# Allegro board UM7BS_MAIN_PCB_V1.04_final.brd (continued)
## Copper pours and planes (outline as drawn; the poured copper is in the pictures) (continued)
VDD33 on BOTTOM (solid shape): 119.28,35.94 119.28,35.89 119.27,35.87 119.23,35.79 119.22,35.7 119.22,35.42 119.11,35.31 118.71,35.31 117.8,34.4 117.8,31.57 117.06,30.83 117.06,29.96 116.76,29.67 114.69,29.67 114.62,29.73 113.35,29.73 113.23,29.86 113.23,31.76 113.3,31.84 114.53,31.84 114.71,32.02 115.93,32.02 116.27,32.36 116.27,33.58 115.98,33.88 115.98,35.21 116.05,35.28 117.02,35.28 117.8,36.06 117.8,36.06 119.15,36.06
VDD33 on LAY4 (solid shape): outline of 746 points within 116.62,31.79 130.86,41.4
VDDIO_8625 on TOP (solid shape): outline of 346 points within 147.79,89.33 153.59,100.76
VDDQ_LX on TOP (solid shape): 199.99,26.54 199.99,22.3 199.68,22 198.69,22 198.69,22 198.22,22 198.05,21.82 198.05,20.95 197.56,20.47 194.71,20.47 194.41,20.77 194.41,26.38 194.83,26.8 199.72,26.8
VIN_LCD on TOP (solid shape): 135.47,94.88 135.55,94.84 135.57,94.76 135.91,94.34 136.26,94.76 136.28,94.84 136.36,94.88 139.01,94.88 139.17,94.72 139.17,93.89 139.65,93.41 139.65,85.62 139.45,85.42 137.2,85.42 136.7,85.92 136.7,89.22 136.13,89.79 135.02,89.79 134.5,90.32 134.5,94.49 134.88,94.88
+V_ADP_IN on TOP (solid shape): outline of 101 points within 129.13,17.63 139.25,25.31
+V_ADP_IN on BOTTOM (solid shape): 141.51,24.33 141.51,21.78 141.42,21.68 138.52,21.68 138.31,21.9 138.31,24.27 138.47,24.44 141.4,24.44
+V_DC on TOP (solid shape): outline of 470 points within 120.04,58.09 149.51,84.38
+V_DC on TOP (solid shape): outline of 843 points within 136.73,7.38 195.12,49.17
+V_DC on BOTTOM (solid shape): 147.33,58.23 147.33,49.97 144.37,47.02 140.41,47.02 140.23,47.19 140.23,59.03 140.78,59.57 145.98,59.57
+V_LED on TOP (solid shape): outline of 160 points within 114.03,92.9 127.3,100.3
+V_LED on BOTTOM (solid shape): 113.69,99.58 119.39,99.58 119.85,99.13 119.85,96.38 119.51,96.05 112.46,96.05 111.62,95.21 111.62,93.53 111.54,93.46 110.03,93.46 109.92,93.56 109.92,95.94 109.85,96.01 109.85,96.07 109.82,96.29 109.71,96.44 109.71,100.14 110.05,100.47 112.8,100.47
+VCORE on TOP (solid shape): 185.82,68.01 185.82,67.88 185.56,67.63 185.56,67.5 185.72,67.35 185.72,67.02 185.31,66.61 185.31,66.23 185.34,66.21 185.34,66.19 185.82,65.71 185.82,65.6 185.69,65.47 184.8,65.47 184.55,65.72 184.55,66.49 183.91,67.12 183.91,67.25 184.42,67.76 184.42,68.01 184.29,68.14 184.29,68.39 184.42,68.52 185.31,68.52
+VCORE on TOP (solid shape): outline of 487 points within 185.96,16.82 196.93,46.68
+VCORE on LAY4 (solid shape): outline of 2918 points within 184.17,37.82 200.04,64.84
+VCORE on VCC5 (solid shape): outline of 3709 points within 182.49,35.7 200.83,68.54
+VGG on TOP (solid shape): outline of 541 points within 162.38,30.38 185.19,43.45
+VGG on BOTTOM (solid shape): 184.44,43.38 184.52,43.39 184.62,43.39 184.74,43.27 184.74,40.14 184.58,39.98 182.59,39.98 182.13,40.44 182.13,43.17 182.35,43.39 184.36,43.39
+VGG on LAY3 (solid shape): 174.78,33.96 174.78,33.69 174.67,33.58 172.89,33.58 172.26,32.95 171.18,32.95 170.86,33.27 170.86,34.17 171.26,34.57 173.05,34.57 173.05,34.52 173.06,34.46 173.08,34.42 173.11,34.37 173.14,34.33 173.18,34.29 173.22,34.26 173.27,34.24 173.32,34.22 173.37,34.22 173.43,34.22 173.48,34.22 173.53,34.24 173.58,34.26 173.62,34.29 173.66,34.33 173.69,34.37 173.72,34.42 173.74,34.46 173.75,34.52 173.75,34.57 173.75,34.62 173.74,34.67 173.72,34.72 173.69,34.77 173.66,34.81 173.62,34.84 173.58,34.87 173.53,34.9 173.48,34.91 173.43,34.92 173.37,34.92 173.32,34.91 173.27,34.9 173.22,34.87 173.18,34.84 173.14,34.81 173.11,34.77 173.08,34.72 173.06,34.67 173.05,34.62 173.05,34.57 171.26,34.57 172.42,35.73 172.58,35.73 172.6,35.75 172.98,35.75
+VGG on LAY4 (solid shape): outline of 3705 points within 170.83,32.94 191.91,60.9
+VGG on VCC5 (solid shape): outline of 2850 points within 182.13,39.27 192.07,61.31
+VNN on TOP (solid shape): 152.62,27.59 152.62,23.45 152.02,22.85 152.02,20.32 151.99,20.24 151.92,20.21 151.66,20.12 151.54,19.87 151.53,19.84 151.49,19.82 149.91,19.82 149.61,19.95 149.32,19.82 148.92,19.82 148.77,19.97 148.77,22.85 149.26,23.34 149.26,27.35 149.69,27.78 152.43,27.78
+VNN on BOTTOM (solid shape): outline of 595 points within 145.58,23.07 165.13,39.38
+VNN on LAY4 (solid shape): outline of 1735 points within 163.36,33.63 183.41,61.79
+VNN on VCC5 (solid shape): outline of 1662 points within 163.02,35.57 183.56,62.58
+VSDIO on BOTTOM (solid shape): 173.43,49.87 173.43,48.16 173.37,48.1 172.79,48.1 172.57,47.88 172.57,47.8 172.56,47.79 172.53,47.66 172.56,47.53 172.57,47.52 172.57,46.72 172.5,46.65 172.02,46.65 171.94,46.73 171.94,47.45 171.76,47.62 171.23,47.62 171.15,47.7 171.15,48.16 171.27,48.28 171.82,48.28 171.98,48.43 171.98,48.62 172.05,48.69 172.65,48.69 172.75,48.79 172.75,49.85 172.85,49.95 173.35,49.95
+VSM on TOP (solid shape): 171.99,24.94 171.99,24.41 171.79,24.22 170.4,24.22 170.06,24.57 167.05,24.57 166.92,24.44 165.8,24.44 165.75,24.47 165.76,24.52 165.84,24.6 166.12,24.6 167.02,25.5 167.53,25.5 167.78,25.75 171.17,25.75
+VSM on TOP (solid shape): 210.46,78.93 210.46,45.32 208.08,42.94 208.08,39.03 207.07,38.02 207.07,38.02 207.07,32.94 203.22,29.09 196.54,29.09 195.3,30.33 195.3,34.74 198.36,37.8 198.37,37.81 198.88,38.32 200.37,39.81 202.61,39.81 204.19,41.39 204.19,47.68 203.29,48.58 198.51,48.58 198.49,48.64 198.47,48.69 198.44,48.73 198.4,48.77 198.36,48.8 198.32,48.82 198.27,48.84 198.21,48.85 198.16,48.85 198.11,48.84 198.06,48.82 198.01,48.8 197.97,48.77 197.94,48.73 197.91,48.69 197.88,48.64 197.86,48.58 196.87,48.58 195.85,49.6 195.85,51.88 200.42,56.45 200.42,76.52 205,76.52 205,61.66 205.25,61.41 207.66,61.41 208.04,61.79 208.04,76.39 207.54,76.9 205.38,76.9 205,76.52 200.42,76.52 200.42,78.55 201.06,79.19 210.2,79.19
+VSM on BOTTOM (solid shape): 221.89,76.65 221.89,62.17 221.76,62.04 221.25,62.04 221.12,62.17 221.12,62.93 221,63.06 220.36,63.06 220.3,63.12 220.3,76.96 220.62,77.28 221.25,77.28
+VSM on BOTTOM (solid shape): outline of 4543 points within 186.58,35.42 210.2,77.15
+VSM on LAY3 (solid shape): outline of 1111 points within 200.42,38.17 222.79,76.77
+VSM on LAY4 (solid shape): 203.85,54.04 203.85,49.08 208.28,44.65 208.28,42.28 208.28,42.27 208.25,42.12 208.28,41.98 208.28,41.97 208.28,36.23 207.17,35.11 202.1,35.11 201.06,36.15 201.06,38.89 203.36,41.19 203.36,45.83 203.56,46.19 203.41,46.57 203.37,46.64 203.4,46.72 203.47,47.32 202.89,47.5 201.23,47.5 200.42,48.31 200.42,55.44 200.68,55.69 202.2,55.69
+VSM on VCC5 (solid shape): outline of 216 points within 200.27,35.27 208.36,55.84
+VSM_VTT on TOP (solid shape): 213.63,38.42 213.63,37.78 213.5,37.66 210.48,37.66 209.95,38.19 209.95,38.42 210.08,38.55 213.5,38.55
+VSM_VTT on TOP (solid shape): 220.94,37.85 220.9,37.77 220.82,37.75 220.78,37.75 220.42,37.55 220.5,37.15 220.51,37.12 220.52,37.08 220.46,37.03 220.42,36.95 220.36,36.9 218.08,36.9 217.95,37.02 217.95,37.93 218.23,38.21 220.94,38.21
+VSM_VTT on TOP (solid shape): 170.45,27.05 171.47,27.05 171.59,26.92 172.18,26.92 174.03,25.08 174.03,24.49 173.92,24.37 173.91,24.37 173.78,24.25 173.08,24.25 171.31,26.02 171.2,26.02 171.2,26.01 167.81,26.01 167.47,25.67 166.93,25.67 166.22,24.96 166.2,24.95 166.09,24.92 165.99,24.85 165.74,24.85 165.61,24.98 165.61,25.74 166.58,26.72 167.06,26.72 167.43,27.08 168.78,27.08 169.04,27.11 169.22,27.31 169.23,27.35 170.15,27.35
+VSM_VTT on BOTTOM (solid shape): 219.84,38.68 219.84,37.88 219.6,37.64 219.6,37.02 219.47,36.9 217.99,36.9 217.17,37.72 209.89,37.72 209.82,37.78 209.82,38.67 209.95,38.8 219.73,38.8
AC_IN on TOP (solid shape): outline of 184 points within 114.5,21.38 124.27,29.17
AUDIO_DVDD_IO on BOTTOM (solid shape): 29.41,33.05 31.06,33.05 31.16,32.95 31.16,30.96 31.06,30.87 30.24,30.87 30.12,30.99 30.12,32.16 29.8,32.48 29.43,32.48 28.79,33.11 28.79,33.12 28.19,33.72 28.19,33.77 28.19,33.78 28.19,33.85 28.26,33.91 28.55,33.91
AXGND on TOP (solid shape): 157.86,15.46 157.86,15.05 157.33,14.51 156.58,14.51 156.13,14.97 155.76,14.97 155.58,15.16 155.58,15.46 155.7,15.58 157.73,15.58
AXGND on TOP (solid shape): 162.72,30.03 162.72,30.01 162.8,29.83 162.98,29.72 162.99,29.72 163.13,29.58 163.13,28.98 162.94,28.79 162.81,28.79 162.31,29.3 160.91,29.3 160.84,29.33 160.81,29.41 160.34,29.95 159.86,29.41 159.84,29.33 159.76,29.3 159.12,29.3 158.83,29.59 158.83,30.28 158.9,30.35 162.4,30.35
AXGND on BOTTOM (solid shape): outline of 491 points within 155.19,14.52 167.88,30.4
EVDD10 on BOTTOM (solid shape): 122.92,45.54 122.92,44.73 122.69,44.51 122.69,43.13 122.3,42.74 122.08,42.74 122.01,42.81 122.01,45.54 122.07,45.6 122.86,45.6
LAN_N1 on BOTTOM (solid shape): 95.3,35.46 95.3,30.23 95.72,29.81 95.72,28.54 95.6,28.42 93.43,28.42 93.31,28.54 93.31,30.13 94.1,30.92 94.1,33.34 93.87,33.58 93.21,33.58 93.11,33.68 93.11,34.67 94.01,35.57 95.19,35.57
LCD_VCC on BOTTOM (solid shape): 130.23,96.75 130.23,92 132.72,89.51 132.72,85.88 133.02,85.58 134.37,85.58 134.6,85.36 134.6,84.5 133.9,83.81 131.25,83.81 130.53,84.52 130.53,86.82 129.88,87.47 129.88,88.94 127.6,91.22 127.6,96.8 127.75,96.95 130.04,96.95
LL1 on TOP (solid shape): 135.56,64.7 135.56,61.43 135.12,60.99 133.29,60.99 132.6,60.3 132.6,58.47 132.45,58.32 130.14,58.32 130.07,58.39 130.07,62.2 129.63,62.64 124.73,62.64 124.67,62.7 124.67,65.17 124.81,65.31 130.95,65.31 130.95,65.31 134.94,65.31
LL2 on TOP (solid shape): outline of 155 points within 109.55,72.45 117.94,78.93
LX3 on TOP (solid shape): 154.88,21.87 155.14,21.75 155.42,21.81 155.56,21.81 155.59,21.78 155.62,21.76 155.73,21.64 156.07,21.64 156.16,21.58 156.13,21.46 155.87,21.46 154.26,19.86 153,19.86 152.91,19.95 152.91,22.47 152.93,22.5 153.04,22.61 154.14,22.61
LX4 on TOP (solid shape): 161.31,17.49 161.65,17.15 161.66,17.14 161.75,16.98 161.9,16.89 161.92,16.88 162.31,16.49 162.31,14.82 162.28,14.69 162.31,14.57 162.31,11.75 162.17,11.61 160.64,11.61 160.53,11.72 160.53,14.44 161.29,15.2 161.29,15.49 161.32,15.52 161.32,16.94 161.29,16.96 161.29,16.98 161.27,17.01 161.24,17.1 161.18,17.19 161.18,17.61 161.31,17.61
LX5 on TOP (solid shape): 159.29,17.27 159.26,17.23 159.26,17.07 159.23,17.05 159.23,15.52 159.26,15.49 159.26,15.46 159.39,15.33 159.39,13.67 158.88,13.16 158.88,12.01 158.59,11.73 157.68,11.73 157.63,11.78 157.63,14.58 158.12,15.07 158.12,16.19 158.57,16.65 158.57,16.93 159.18,17.53 159.18,17.61 159.29,17.61
OVPA on TOP (solid shape): 115.54,100.51 115.54,98.42 115.42,98.31 114.01,98.31 113.91,98.41 113.91,100.6 114,100.68 115.37,100.68
REGOUT on BOTTOM (solid shape): 123.62,36.53 123.72,36.48 123.83,36.46 124.22,36.46 125.19,35.49 125.31,35.49 126.01,34.79 126.05,34.79 126.06,34.78 128.05,34.78 128.3,34.54 128.3,33.4 128.17,33.27 124.99,33.27 124.87,33.4 124.87,34.16 123.47,35.55 123.47,36.44 123.57,36.54 123.6,36.54
SODIMM_VREF_CA0 on BOTTOM (solid shape): 220.87,62.68 220.87,62.17 221.51,61.53 221.51,60.01 220.87,59.37 220.36,59.37 220.24,59.5 220.24,62.55 220.49,62.8 220.74,62.8
VGG_LX on TOP (solid shape): 159.19,37.06 159.19,32.32 158.87,32 155.1,32 154.55,32.55 149.49,32.55 149.42,32.62 149.42,35.22 149.46,35.26 154.52,35.26 154.83,35.57 154.83,36.08 154.93,36.18 155.72,36.18 156.24,36.71 156.28,36.71 156.28,37.16 156.39,37.28 158.98,37.28
N926610 on BOTTOM (solid shape): 175.2,48.57 175.2,47.92 175.34,47.78 175.92,47.78 176,47.7 176,47.26 175.92,47.18 174.7,47.18 174.56,47.33 174.56,48.57 174.61,48.61 175.16,48.61
N1061235 on BOTTOM (solid shape): 32.09,39.99 32.09,39.04 31.97,38.93 31.25,38.93 30.75,38.42 30.75,37.26 30.61,37.13 29.58,37.13 29.4,36.95 28.27,36.95 28.23,36.99 28.23,37.38 28.26,37.4 28.45,37.4 29.63,38.58 29.64,38.58 31.09,40.02 32.05,40.02
N6550170 on BOTTOM (solid shape): 155.52,92.99 155.52,92.98 155.59,92.88 155.7,92.8 155.71,92.8 155.9,92.6 155.94,92.56 155.99,92.52 158.12,90.39 158.86,90.39 158.98,90.27 158.98,88.92 158.84,88.78 155.65,88.78 155.52,88.91 155.52,91.3 155.52,91.3 155.52,91.43 154.58,92.36 154.58,93.08 154.67,93.16 155.34,93.16
N6697991 on BOTTOM (solid shape): 139.18,87.27 139.18,83.29 139,83.11 135.71,83.11 135.44,83.38 135.44,85.46 135.61,85.64 136.82,85.64 137.05,85.86 137.05,87.24 137.27,87.47 138.98,87.47
N6835729 on TOP (solid shape): 115.29,28.19 115.29,26.86 115.15,26.71 112.73,26.71 112.62,26.82 112.62,28.14 112.79,28.31 115.18,28.31
N6950609 on BOTTOM (solid shape): 143.74,44.12 143.74,42.79 143.32,42.37 143.32,41.76 143.14,41.59 141.53,41.59 141.42,41.7 141.42,42.41 141.47,42.46 142.2,42.46 142.75,43 142.75,44.1 142.91,44.27 143.59,44.27
N7256343 on TOP (solid shape): 180.87,25.69 180.87,24.8 180.74,24.67 179.22,24.67 179.09,24.8 179.09,25.69 179.22,25.82 180.74,25.82
N16968245 on TOP (solid shape): 129.41,96.67 129.41,93.87 129.69,93.59 131.07,93.59 131.42,93.24 131.42,89.52 130.92,89.02 129.69,89.02 129.67,89.06 129.42,89.26 129.12,89.18 129.09,89.16 129.06,89.17 128.93,89.24 128.78,89.24 128.63,89.18 128.52,89.05 128.51,89.02 120.01,89.02 119.99,89.03 119.85,89.06 119.7,89.03 119.69,89.02 118.51,89.02 117.98,89.55 117.98,94.97 118.23,95.22 123.41,95.22 123.79,94.84 123.79,93.06 124.5,92.36 127.23,92.36 127.75,92.87 127.75,96.56 128,96.81 129.27,96.81
N17285117 on TOP (solid shape): 126.12,26.28 129.78,26.28 130.33,25.73 130.33,21.66 129.9,21.23 125.24,21.23 124.84,21.63 124.84,26.05 125.07,26.29 126.11,26.29
N17585502 on TOP (solid shape): 131.81,96.63 131.81,95.65 131.7,95.55 130.08,95.55 129.94,95.69 129.94,96.6 130.05,96.7 131.74,96.7
N72573691 on TOP (solid shape): 155.77,38.47 155.77,36.73 155.71,36.67 154.87,36.67 154.82,36.72 154.82,38.52 154.87,38.57 155.67,38.57
N72594291 on TOP (solid shape): 199.47,21.46 199.47,19.81 199.37,19.71 198.78,19.71 198.67,19.82 198.67,20.34 198.3,20.71 198.3,21.44 198.39,21.53 199.41,21.53

Small or netless copper shapes (teardrops, artwork), in the pictures only: 22 on TOP, 3 on BOTTOM

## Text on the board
Ref Des/Silkscreen Bottom: UM7BS_MAIN_PCB | REF | BOTTOM | V1.04 | 5000-0006-1304 | 2016.0617.1800
User.Comments: PARTITION_2
Ref Des/Silkscreen Top: UM7BS_MAIN_PCB | 2016.0617.1800 | TOP | TB | TA | 5000-0006-1304 | V1.04 | REF
User.25: FIGURE | SIZE | 9.84 | 15.75 | 27.56 | 31.5 | 37.4 | 62.99 | 90.55 | 98.43 | 133.86 | 39.37 | 43.0 | 43.31 | 51.18 | 55.12 | 59.06 | 63.0 | 78.74 | 125.98 | 59.06x23.62 | 94.49x23.62 | 98.43x35.43 | 102.36x39.37 | DRILL CHART: TOP to BOTTOM | ALL UNITS ARE IN MILS | TOLERANCE | +0.0/-0.0 | +2.0/-2.0 | PLATED | NON-PLATED | QTY | 2480 | 902 | 10 | 2 | 8 | 5 | 4 | 3 | 1 | 6
User.27: +V1.05A | +VSM | +VCORE | +VNN | +VGG | GND | AGND
User.28: GND | AGND
